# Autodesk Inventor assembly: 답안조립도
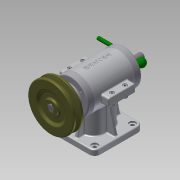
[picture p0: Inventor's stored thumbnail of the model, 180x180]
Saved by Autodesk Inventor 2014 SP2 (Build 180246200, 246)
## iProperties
Created: 2015-12
Part Number: 답안조립도
Document SubType Name: Assembly
Designer: Administrator
Author: Administrator
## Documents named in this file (19)
- C:\Users\Administrator\Desktop\351207V1007\답안조립도.iam
- C:\Users\Administrator\Desktop\351207V1007\본체.ipt
- C:\Users\Administrator\Desktop\351207V1007\베어링 6202.ipt
- C:\Users\Administrator\Desktop\351207V1007\키 4 x 4 x 18.ipt
- C:\Users\Administrator\Desktop\351207V1007\편심축.ipt
- C:\Users\Administrator\Desktop\351207V1007\앞커버.ipt
- C:\Users\Administrator\Desktop\351207V1007\오일실 12 22 7.ipt
- C:\Users\Administrator\Desktop\351207V1007\뒤커버.ipt
- C:\Users\Administrator\Desktop\351207V1007\베어링 6201.ipt
- C:\Users\Administrator\Desktop\351207V1007\스프링.ipt
- C:\Users\Administrator\Desktop\351207V1007\슬라이드.ipt
- C:\Users\Administrator\Desktop\351207V1007\본체커버.ipt
- C:\Users\Administrator\Desktop\351207V1007\볼트 M3x0.5x8.ipt
- C:\Users\Administrator\Desktop\351207V1007\V-벨트풀리.ipt
- C:\Users\Administrator\Desktop\351207V1007\멈춤나사 M3x8.ipt
- C:\Users\Administrator\Desktop\351207V1007\볼트 M4 x 16.ipt
- C:\Users\Administrator\Desktop\351207V1007\너트 M4.ipt
- C:\Users\Administrator\Desktop\351207V1007\와셔 ST 4-100.ipt
- C:\Users\Administrator\Desktop\351207V1007\레바.ipt
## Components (13 placed, 4 different names)
1. V-벨트풀리:1
2. ISO 4762 M4 x 16:1
3. ISO 4762 M4 x 16:2
4. ISO 4762 M4 x 16:3
5. ISO 4762 M4 x 16:4
6. ISO 4032 M4:1
7. ISO 7091 ST 4 - 100 HV:1
8. ISO 4032 M4:2
9. ISO 7091 ST 4 - 100 HV:2
10. ISO 4032 M4:3
11. ISO 7091 ST 4 - 100 HV:3
12. ISO 4032 M4:4
13. ISO 7091 ST 4 - 100 HV:4
